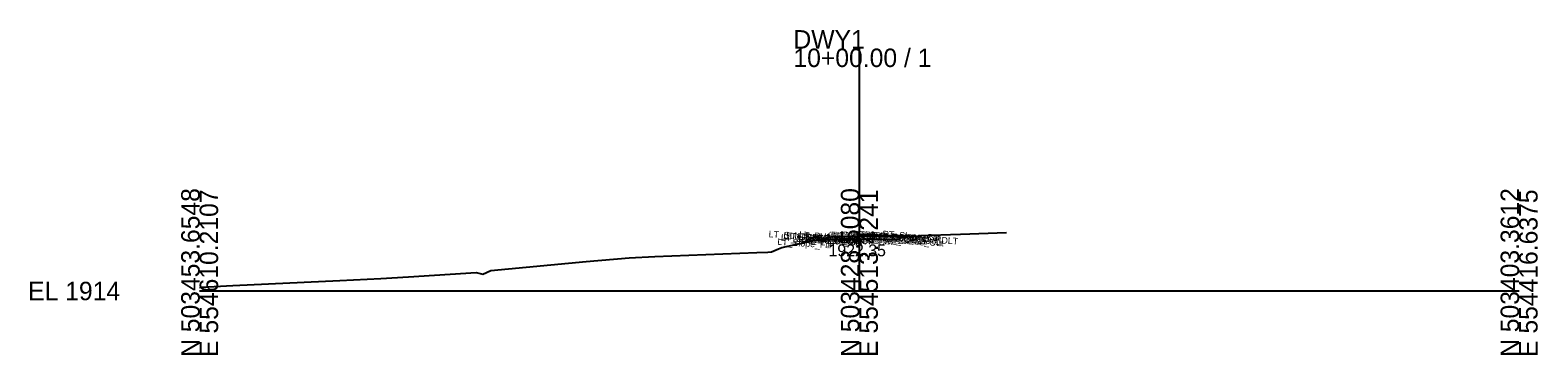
# Model space of a CAD drawing. Extents: x -26 to 203, y -10 to 1558.
# Drawn here: x -25.7 to 202.8, y -9.7 to 39.6 of the extents above; entities that cross this region are included whole.
import ezdxf

# ---------------------------------------------------------------- set-up
doc = ezdxf.new("R2010")
doc.units = 0
for name, color, linetype in [('Default', 7, 'Continuous'), ('Exist Cross Section Cell', 7, 'Continuous'), ('Exist XS Center Line Elevation Label', 7, 'Continuous'), ('Exist XS Ground Line', 7, 'Continuous'), ('Prop XS Earthwork Shape', 7, 'Continuous'), ('Typical Text Asphalt at Bridge Approach CELL', 7, 'Continuous')]:
    doc.layers.add(name, color=color, linetype=linetype)

msp = doc.modelspace()

# ---------------------------------------------------------------- linework, layer by layer
at = {"layer": 'Exist Cross Section Cell'}
for p, q in [((100, 0), (100, 36.78)), ((0, 0), (100, 0)), ((100, 0), (200, 0))]:
    msp.add_line(p, q, dxfattribs=at)
at = {"layer": 'Exist XS Ground Line'}
for p, q in [((88.23, 6.58), (95.4, 8.16)), ((95.4, 8.16), (95.98, 8.27)), ((95.98, 8.27), (96.82, 8.29)), ((96.82, 8.29), (100, 8.35)), ((100, 8.35), (104.98, 8.46)), ((104.98, 8.46), (108.95, 8.34)), ((108.95, 8.34), (109.32, 8.41)), ((109.32, 8.41), (115.34, 8.63)), ((115.34, 8.63), (122.3, 8.87)), ((58.58, 4.48), (65.11, 5.03)), ((65.11, 5.03), (69.01, 5.22)), ((69.01, 5.22), (84.46, 5.82)), ((84.46, 5.82), (86.1, 5.88)), ((86.1, 5.88), (86.69, 5.94)), ((86.69, 5.94), (87.76, 6.38)), ((87.76, 6.38), (88.23, 6.58)), ((31.67, 2.13), (41.9, 2.8)), ((41.9, 2.8), (42.91, 2.57)), ((42.91, 2.57), (44.13, 3.13)), ((44.13, 3.13), (58.58, 4.48)), ((0, 0.55), (0.33, 0.57)), ((0.33, 0.57), (5.02, 0.81)), ((5.02, 0.81), (21.25, 1.6)), ((21.25, 1.6), (27.47, 1.88)), ((27.47, 1.88), (31.67, 2.13))]:
    msp.add_line(p, q, dxfattribs=at)
at = {"layer": 'Prop XS Earthwork Shape'}
for points in [[(91.32, 7.26), (93.9, 7.83), (93.58, 8.15), (93, 8.1)], [(96.82, 8.29), (100, 8.36), (105, 8.26), (106.42, 8.15), (106.01, 7.74), (105, 7.76), (100, 7.86), (95, 7.76), (93.99, 7.74), (93.9, 7.83), (95.4, 8.16), (95.98, 8.27)], [(100, 8.36), (104.98, 8.46), (107.56, 8.38), (107, 8.1), (106.42, 8.15), (105, 8.26)]]:
    msp.add_lwpolyline(points, close=True, dxfattribs=at)

# ---------------------------------------------------------------- texts
at = {"layer": 'Default'}
msp.add_text('-', height=0.0001, dxfattribs=at).set_placement((0, 0))
at = {"layer": 'Exist Cross Section Cell'}
for s, p in [('DWY1', (90, 36.78)), ('10+00.00 / 1', (90, 33.98)), ('EL 1914', (-26, -1.4))]:
    msp.add_text(s, height=2.8, dxfattribs=at).set_placement(p)
for s, p in [('N 503453.6548', (0, -10)), ('E 554610.2107', (2.8, -10)), ('N 503428.5080', (100, -10)), ('E 554513.4241', (102.8, -10)), ('N 503403.3612', (200, -10)), ('E 554416.6375', (202.8, -10))]:
    msp.add_text(s, height=2.8, rotation=90, dxfattribs=at).set_placement(p)
at = {"layer": 'Exist XS Center Line Elevation Label'}
msp.add_text('1922.35', height=1.8, dxfattribs=at).set_placement((95.32, 5.27))
at = {"layer": 'Typical Text Asphalt at Bridge Approach CELL'}
for s, p in [('LT_Sub_Trench_Out_DLT', (86.22, 8.16)), ('RT_Sub_Trench_Out_DLT', (98.99, 8.16)), ('RT_Slope_Cut', (103.48, 8.16)), ('LT_Slope_Fill', (87.54, 7.02)), ('LT_Sub_Trench_Out', (88.08, 7.65)), ('LT_GS_OS_CTL', (88.44, 7.92)), ('LT_PS2_Shelf_Out', (88.88, 7.87)), ('LT_PS2_OEOP', (90.51, 7.8)), ('LT_PV2_OEOT', (90.72, 7.81)), ('LT_Sub_OEOT', (90.74, 7.56)), ('LT_PV1_OEOT', (90.84, 8.05)), ('RT_PV2_OEEOP', (95.31, 7.94)), ('RT_Sub_OEEOP', (95.33, 7.68)), ('LT_PV2_OEEOP', (95.37, 7.93)), ('LT_Sub_OEEOP', (95.39, 7.68)), ('RT_PV1_OEEOP', (95.43, 8.05)), ('LT_PV1_OEEOP', (95.49, 8.05)), ('RT_PV2_IEEOP', (95.69, 7.91)), ('LT_PV2_IEEOP', (95.75, 7.9)), ('RT_PV1_IEEOP', (95.81, 8.03)), ('LT_PV1_IEEOP', (95.87, 8.02)), ('PV2_PGL', (97.32, 7.79)), ('PV1_PGL', (97.44, 8.04)), ('RT_Sub_Trench_Out', (100.04, 7.65)), ('RT_PS2_Shelf_Out', (100.33, 7.87)), ('RT_PV2_OEOT', (100.66, 7.81)), ('RT_Sub_OEOT', (100.69, 7.56)), ('RT_PV1_OEOT', (100.78, 8.05)), ('RT_PS2_OEOP', (100.96, 7.8)), ('RT_GS_OS_CTL', (102.38, 7.92))]:
    msp.add_text(s, height=1, rotation=356, dxfattribs=at).set_placement(p)

doc.saveas('drawing.dxf')
